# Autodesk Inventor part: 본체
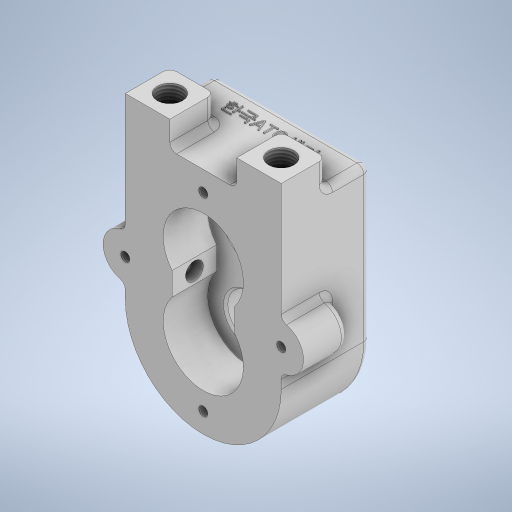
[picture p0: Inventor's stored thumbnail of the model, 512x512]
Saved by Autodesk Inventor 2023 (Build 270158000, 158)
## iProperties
Created: 2024-03
Part Number: 본체
Material: 일반
Document SubType Name: Modeling
Designer: asung
Density: 1 g/cm^3
Appearance: 기본값
Author: asung
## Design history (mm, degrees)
sketch "스케치1"
  geometry: L1 (0, 0)-(0, 33); L2 (0, 33)-(0, 68); L3 (-35, 68)-(35, 68); L4 (35, 68)-(35, 0); L5 (35, 0)-(-35, 0); L6 (-35, 0)-(-35, 68); L7 (0, 0)-(0, -26); C1 r 35 at (0, 0); 3 further points
  constraints: 14 end point, 2 coincident, 2 parallel, 2 vertical, 1 centre point, 1 horizontal, 1 midpoint, 1 perpendicular, 1 point on line
  dimensions: "d1" = 33 distance of L1.start L1.end; "d2" = 35 distance of L1.end L2.end; "d5" = 70 diameter of C1; "d6" = 70 distance of L4.end L5.end; "d7" = 68 distance of L3.end L4.end; "d8" = 26 distance of L7.start L7.end
extrude "돌출1" new body sketch "스케치1" stored distance "d9" = 40; taper "d10" = 0 deg
sketch "스케치3"
  geometry: L1 (0, 0)-(0, 33); L2 (14, 0)-(14, 33); L3 (-14, 0)-(-14, 33); C1 r 18 at (0, 0); C2 r 18 at (0, 33); 5 further points
  constraints: 6 end point, 2 centre point, 2 coincident, 2 parallel, 1 vertical
  dimensions: "d12" = 36 diameter of C1; "d13" = 33 distance of L1.start L1.end; "d14" = 36 diameter of C2; "d15" = 28 distance of L2.start L3.start; "d16" = 28 distance between parallel lines of L2 L3; "d17" = 33 distance of L2.start L2.end; "d18" = 28 distance of L2.end L3.end; "d19" = 14 distance between parallel lines of L1 L2; "d20" = 35.8469 distance of point (0, 0) L2.end
extrude "돌출2" cut sketch "스케치3" distance "d21" = 20; taper "d22" = 0 deg
node "작업 평면1"
sketch "스케치6"
  geometry: C1 r 7.5 at (0, 33) reference; 2 further points
  constraints: 1 coincident
hole "구멍2" sketch "스케치6" at (0, 33) diameter "d35" = 20; stored, may be unused: countersink angle "d39" = 90 deg, drill point angle "d41" = 0 deg; dims "d36" = 6, "d37" = 25, "d38" = 7.3, "d40" = 10
sketch "스케치7"
  geometry: A1 r 18 centre (0, 0) between (-14, 11.314) and (14, 11.314) reference; 2 further points
  constraints: 1 coincident
hole "구멍3" sketch "스케치7" at (0, 0) diameter "d42" = 20; stored, may be unused: countersink angle "d46" = 90 deg, drill point angle "d48" = 0 deg; dims "d43" = 6, "d44" = 4, "d45" = 2, "d47" = 10
sketch "스케치8"
  geometry: L1 (0, 0)-(0, -26); L2 (35, 68)-(-35, 68) reference; L3 (-35, 68)-(-35, 0) reference; L4 (35, 0)-(35, 68) reference; L5 (-14, 11.314)-(-14, 21.686) reference; L6 (14, 21.686)-(14, 11.314) reference; L7 (0, 33)-(0, 59); A1 r 35 centre (0, 0) between (-35, 0) and (35, 0) reference; A2 r 18 centre (0, 0) between (-14, 11.314) and (14, 11.314) reference; A3 r 18 centre (0, 33) between (14, 21.686) and (-14, 21.686) reference; 2 further points
  constraints: 4 end point, 2 coincident, 2 vertical
  dimensions: "d49" = 26 distance of L1.start L1.end; "d50" = 26 distance of L7.start L7.end
  node "투영된 루프3"
chamfer "모따기2" distance "d54" = 1; stored, may be unused: second distance "d55" = 2, angle "d56" = 30 deg
hole "구멍4" sketch "스케치8" diameter "d57" = 4.134; stored, may be unused: countersink angle "d61" = 90 deg, drill point angle "d63" = 118 deg; dims "d58" = 10, "d59" = 4, "d60" = 2, "d62" = 12
sketch "스케치9"
  geometry: L1 (35, 68)-(-35, 68) reference; L2 (-35, 68)-(-35, 0) reference; L3 (35, 0)-(35, 68) reference; L4 (0, 0)-(0, 33); C1 r 26 at (0, 33); A1 r 35 centre (0, 0) between (-35, 0) and (35, 0) reference; 1 further point
  constraints: 2 end point, 1 centre point, 1 coincident, 1 vertical
  dimensions: "d65" = 33 distance of L4.start L4.end; "d66" = 52 diameter of C1
extrude "돌출4" join sketch "스케치9" distance "d67" = 3.3; taper "d68" = 0 deg
sketch "스케치10"
  geometry: C1 r 26 at (0, 0) reference; C2 r 16 at (0, 0); 1 further point
  constraints: 1 centre point, 1 coincident
  dimensions: "d69" = 32 diameter of C2
extrude "돌출5" join sketch "스케치10" distance "d70" = 4; taper "d71" = 0 deg
sketch "스케치11"
  geometry: C1 r 16 at (0, 0) reference; 2 further points
  constraints: 1 coincident
hole "구멍5" sketch "스케치11" at (0, 0) diameter "d72" = 15; stored, may be unused: countersink angle "d76" = 90 deg, drill point angle "d78" = 0 deg; dims "d73" = 10, "d74" = 25, "d75" = 7.3, "d77" = 80
fillet "모깎기2" dims "d79" = 3
chamfer "모따기3" distance "d80" = 1; stored, may be unused: second distance "d81" = 2, angle "d82" = 30 deg
chamfer "모따기4" distance "d83" = 0.7; stored, may be unused: second distance "d84" = 2, angle "d85" = 30 deg
sketch "스케치13" dims "d86" = 42
  geometry: C1 r 12.5 at (0, 0) reference; C2 r 16 at (0, 0) reference; C3 r 26 at (0, 0) reference; 3 further points
  constraints: 1 coincident, 1 vertical alignment, 2 other
hole "구멍6" sketch "스케치13" at (0, 21) diameter "d87" = 3.242; stored, may be unused: countersink angle "d91" = 90 deg, drill point angle "d93" = 118 deg; dims "d88" = 8, "d89" = 25, "d90" = 7.3, "d92" = 10
sketch "스케치14"
  geometry: L1 (-14, 11.314)-(-14, 21.686) reference; L2 (14, 21.686)-(14, 11.314) reference; L3 (35, 68)-(-35, 68) reference; L4 (-35, 68)-(-35, 0) reference; L5 (35, 0)-(35, 68) reference; L6 (35, 68)-(15, 68); L7 (15, 68)-(15, 80); L8 (15, 80)-(35, 80); L9 (35, 80)-(35, 68); L10 (-35, 68)-(-15, 68); L11 (-15, 68)-(-15, 80); L12 (-15, 80)-(-35, 80); L13 (-35, 80)-(-35, 68); L14 (-35, 80)-(-35, 16.5); C1 r 2.067 at (0, -26) reference; C2 r 2.067 at (0, 59) reference; C3 r 10 at (-35, 16.5); A1 r 18 centre (0, 33) between (14, 21.686) and (-14, 21.686) reference; A2 r 18 centre (0, 0) between (-14, 11.314) and (14, 11.314) reference; A3 r 35 centre (0, 0) between (-35, 0) and (35, 0) reference; 5 further points
  constraints: 18 end point, 4 parallel, 2 horizontal, 2 perpendicular, 1 centre point, 1 coincident, 1 point on line
  dimensions: "d97" = 20 distance of L7.end L8.end; "d98" = 12 distance of L6.end L7.end; "d99" = 20 distance of L12.end L11.end; "d100" = 12 distance of L11.end L10.end; "d104" = 10 radius of C3; "d105" = 63.5 distance of L14.end L12.end
  node "투영된 루프7"
extrude "돌출6" join sketch "스케치14" distance "d106" = 20; taper "d107" = 0 deg
extrude "돌출7" join sketch "스케치14" distance "d108" = 20; taper "d109" = 0 deg
sketch "스케치15"
  geometry: C1 r 11 at (0, 0) reference; 2 further points
  constraints: 1 coincident
hole "구멍7" sketch "스케치15" at (0, 0) diameter "d110" = 14; stored, may be unused: countersink angle "d114" = 90 deg, drill point angle "d116" = 120 deg; dims "d111" = 8, "d112" = 4, "d113" = 2, "d115" = 10
fillet "모깎기3" dims "d117" = 3
fillet "모깎기4" dims "d118" = 3
fillet "모깎기5" dims "d119" = 3
fillet "모깎기6" dims "d120" = 3
fillet "모깎기7" dims "d121" = 3
sketch "스케치16"
  geometry: A1 r 10 centre (-35, 16.5) between (-37.308, 26.23) and (-37.308, 6.77) reference; A2 r 10 centre (35, 16.5) between (37.308, 6.77) and (37.308, 26.23) reference; 3 further points
  constraints: 2 coincident
hole "구멍8" sketch "스케치16" at (-35, 16.5), (35, 16.5) diameter "d122" = 4.134; stored, may be unused: countersink angle "d126" = 90 deg, drill point angle "d128" = 118 deg; dims "d123" = 10, "d124" = 4, "d125" = 2, "d127" = 12
sketch "스케치17"
  geometry: L1 (57, 0)-(49.308, 0) reference; 2 further points
  constraints: 1 vertical alignment, 1 other
  dimensions: "d129" = 30 distance from line of point (12, 30) L1
feature "엠보싱1" sketch "스케치17" dims "d1" = 33, "d2" = 35, "d5" = 70, "d6" = 70, "d7" = 68, "d8" = 26, "d12" = 36, "d13" = 33, "d14" = 36, "d15" = 28, "d16" = 28, "d17" = 33, "d18" = 28, "d19" = 14, "d20" = 35.8469, "d130" = 0.5, "d131" = 0
sketch "스케치19"
  geometry: L1 (3, 20)-(17, 20) reference; L2 (0, 0)-(0, 17) reference; L3 (20, 0)-(0, 0) reference; L4 (20, 0)-(20, 17) reference; L5 (53, 20)-(67, 20) reference; L6 (50, 0)-(50, 17) reference; L7 (70, 0)-(50, 0) reference; L8 (70, 0)-(70, 17) reference; L9 (10, 0)-(10, 10); L10 (60, 0)-(60, 10); A1 r 3 centre (17, 17) between (20, 17) and (17, 20) reference; A2 r 3 centre (3, 17) between (3, 20) and (0, 17) reference; A3 r 3 centre (67, 17) between (70, 17) and (67, 20) reference; A4 r 3 centre (53, 17) between (53, 20) and (50, 17) reference; 3 further points
  constraints: 4 end point, 2 coincident, 2 midpoint, 2 vertical
  dimensions: "d132" = 10 distance of L9.start L9.end; "d133" = 10 distance of L10.start L10.end
hole "구멍9" sketch "스케치19" at (10, 10), (60, 10) diameter "d134" = 10.7188; stored, may be unused: countersink angle "d140" = 82 deg, drill point angle "d142" = 0 deg; dims "d135" = 8.60806, "d136" = 0.62479, "d137" = 10.82065, "d138" = 4, "d139" = 2, "d141" = 16
sketch "스케치20"
  geometry: L1 (20, -22.627)-(20, 0) reference; L2 (20, 0)-(20, 10.373) reference; L3 (20, 10.373)-(20, 33) reference; L4 (20, 33)-(0, 33) reference; L5 (0, 33)-(0, 57.45) reference; L6 (0, 57.45)-(17, 57.45) reference; L7 (21.472, 56.686)-(30.254, 56.686) reference; L8 (30.254, 56.686)-(30.254, 57.186) reference; L9 (30.254, 57.186)-(30.648, 57.186) reference; L10 (30.648, 57.186)-(30.648, 56.686) reference; L11 (30.648, 56.686)-(37, 56.686) reference; L12 (40, 53.686)-(40, 47.083) reference; L13 (43, 43.595)-(43.3, 43.595) reference; L14 (43.3, 43.595)-(43.3, 29.432) reference; L15 (43.3, 29.432)-(46.3, 29.432) reference; L16 (47.3, 27.071)-(47.3, 16.301) reference; L17 (46.3, 13.94)-(43.3, 13.94) reference; L18 (43.3, 13.94)-(43.3, -0.223) reference; L19 (43.3, -0.223)-(43, -0.223) reference; L20 (40, -3.711)-(40, -40.089) reference; L21 (37, -43.392)-(0, -43.392) reference; L22 (0, -43.392)-(0, -22.627) reference; L23 (0, -22.627)-(20, -22.627) reference; L24 (20, 0)-(0, 0) reference; L25 (0, 0)-(0, 10.373) reference; L26 (0, 10.373)-(20, 10.373) reference; L27 (0, 5.186)-(10, 5.186); A1 r 3 centre (37, 53.686) between (40, 53.686) and (37, 56.686) reference; 2 further points
  constraints: 2 end point, 1 coincident, 1 horizontal, 1 midpoint, 6 other
  dimensions: "d143" = 10 distance of L27.start L27.end
hole "구멍10" sketch "스케치20" at (10, 5.186) diameter "d144" = 8; stored, may be unused: countersink angle "d148" = 90 deg, drill point angle "d150" = 0 deg; dims "d145" = 8.608, "d146" = 4, "d147" = 2, "d149" = 5
node "솔리드1"
pattern_circular "원형 패턴1" dims angle "d95" = 360 deg
mirror "미러1"
mirror "미러2"
node "투영된 루프4"
node "투영된 루프5"
node "투영된 루프8"
node "투영된 루프9"
node "절단 모서리 투영2"
node "절단 모서리 투영3"
feature "A9D066F2-1C7D-4E18-AEED-F7BC21143FA4" dims "d35" = 20, "d36" = 6, "d37" = 25, "d38" = 7.3, "d39" = 90 deg, "d40" = 10, "d41" = 0
